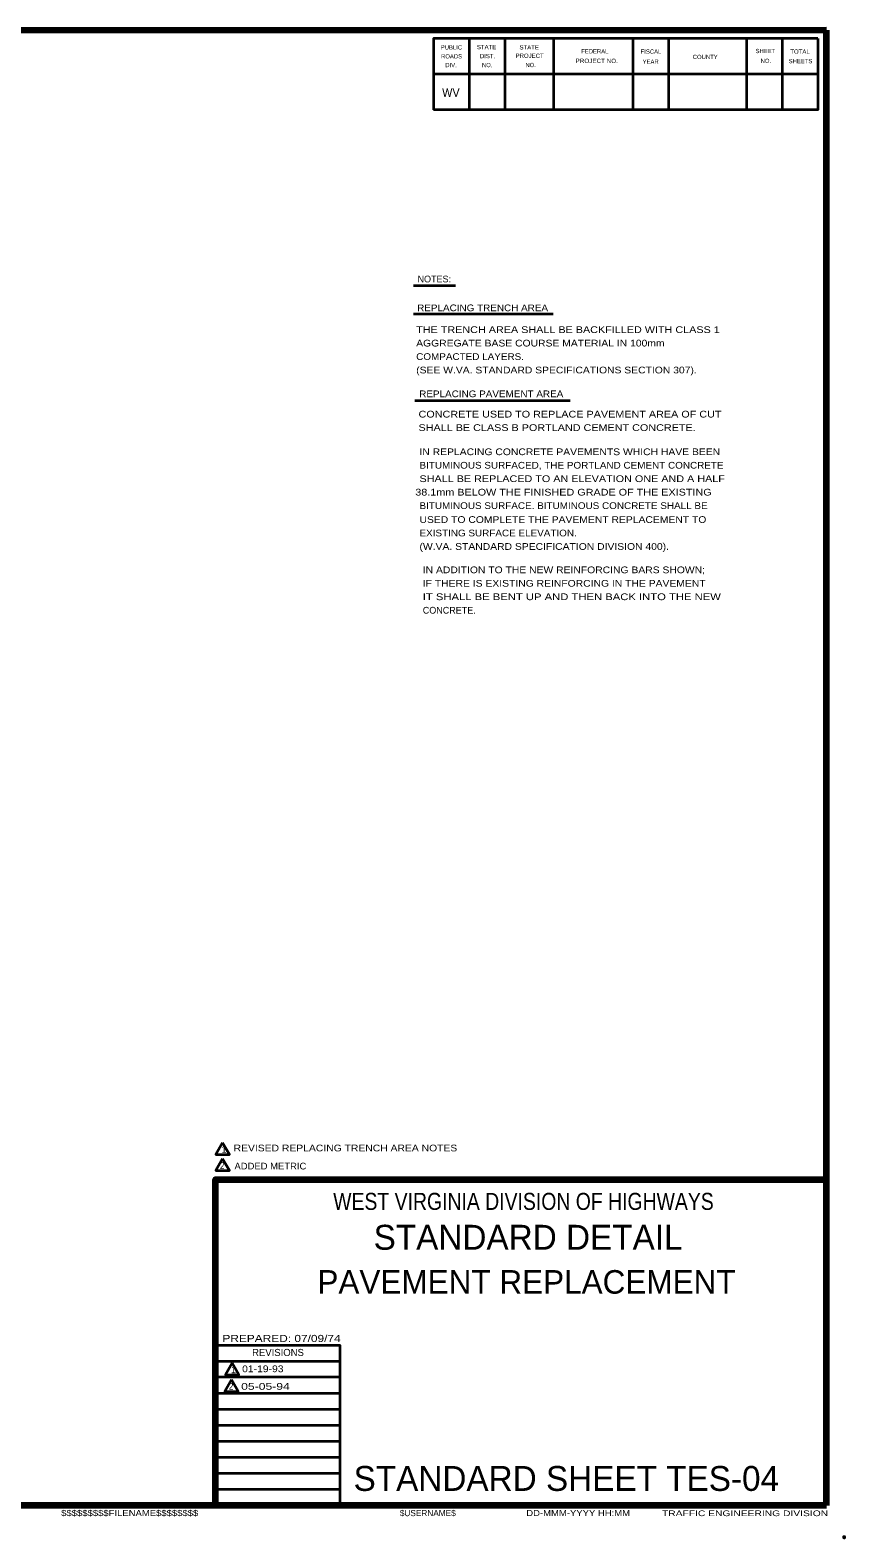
# Model space of a CAD drawing. Extents: x -617 to 238, y 23 to 567.
# Drawn here: x -52 to 238, y 23 to 560 of the extents above; entities that cross this region are included whole.
import ezdxf
from ezdxf.enums import TextEntityAlignment as Align

# ---------------------------------------------------------------- set-up
doc = ezdxf.new("R2010")
doc.units = 0
doc.header["$LTSCALE"] = 0.96
doc.header["$PDMODE"] = 32
doc.header["$PDSIZE"] = 0.48
doc.layers.add('1', color=7, linetype='Continuous', lineweight=40)
doc.layers.add('61', color=7, linetype='Continuous', lineweight=35)

msp = doc.modelspace()

# ---------------------------------------------------------------- linework, layer by layer
at = {"layer": '1', "lineweight": 158}
for q in [(231.8054, 560.3585), (231.8054, 150.5585), (-559.7946, 34.2585)]:
    msp.add_line((231.8054, 34.2585), q, dxfattribs=at)
at = {"layer": '1', "lineweight": 13}
msp.add_line((231.8054, 34.2585), (231.8054, 560.3585), dxfattribs=at)
at = {"layer": '1', "lineweight": 35}
for p, q in [((84.4359, 469.2756), (99.4217, 469.2756)), ((84.4359, 459.2218), (134.3257, 459.2218)), ((85.005, 428.3018), (140.3957, 428.3018)), ((58.3054, 85.6585), (13.8054, 85.6585)), ((58.3054, 79.9585), (13.8054, 79.9585)), ((58.3054, 74.1585), (13.8054, 74.1585)), ((58.3054, 68.4585), (13.8054, 68.4585)), ((58.3054, 62.7585), (13.8054, 62.7585)), ((58.3054, 57.0585), (13.8054, 57.0585)), ((58.3054, 51.3585), (13.8054, 51.3585)), ((58.3054, 45.6585), (13.8054, 45.6585)), ((58.3054, 39.9585), (13.8054, 39.9585))]:
    msp.add_line(p, q, dxfattribs=at)
at = {"layer": '1', "lineweight": 158}
for points in [[(231.8054, 560.3585), (-559.8946, 560.2585), (-559.7946, 34.2585)], [(13.8054, 34.2585), (13.8054, 150.5585), (231.8054, 150.5585)]]:
    msp.add_lwpolyline(points, dxfattribs=at)
at = {"layer": '1', "lineweight": 35}
for points in [[(16.3876, 163.6175), (13.9876, 159.4606), (18.7876, 159.4606)], [(16.3876, 157.8538), (13.9876, 153.6969), (18.7876, 153.6969)], [(19.7828, 85.0323), (17.3828, 80.8754), (22.1828, 80.8754)], [(19.5399, 79.0965), (17.1399, 74.9396), (21.9399, 74.9396)]]:
    msp.add_lwpolyline(points, close=True, dxfattribs=at)
msp.add_lwpolyline([(58.3054, 34.2585), (58.3054, 91.3585), (13.8054, 91.3585)], dxfattribs=at)
at = {"layer": '1'}
msp.add_point((238.1054, 22.9585), dxfattribs=at)
at = {"layer": '61'}
for p, q in [((104.3054, 557.3585), (104.3054, 531.9585)), ((117.0054, 557.3585), (117.0054, 531.9585)), ((134.4054, 557.3585), (134.4054, 531.9585)), ((162.7054, 557.3585), (162.7054, 531.9585)), ((175.4054, 557.3585), (175.4054, 531.9585)), ((203.3054, 557.3585), (203.3054, 531.9585)), ((216.0054, 557.3585), (216.0054, 531.9585)), ((228.7054, 544.6585), (91.6054, 544.6585))]:
    msp.add_line(p, q, dxfattribs=at)
at = {"layer": '61', "lineweight": 53}
for q in [(79.1054, 34.2585), (79.1054, 34.2585), (79.1054, 34.2585), (79.4054, 34.2585), (79.4054, 34.2585)]:
    msp.add_line((231.8054, 34.2585), q, dxfattribs=at)
at = {"layer": '61'}
for points in [[(228.7054, 557.3585), (91.6054, 557.3585), (91.6054, 531.9585)], [(228.7054, 557.3585), (228.7054, 531.9585), (91.6054, 531.9585)]]:
    msp.add_lwpolyline(points, dxfattribs=at)

# ---------------------------------------------------------------- texts
at = {"layer": '1'}
for s, height, width, p in [('WV', 3.048, 0.95, (94.7054, 536.5585)), ('REPLACING TRENCH AREA', 2.4, 1.1, (85.7812, 460.1271)), ('THE TRENCH AREA SHALL BE BACKFILLED WITH CLASS 1', 2.4, 1.2, (85.4396, 452.3537)), ('AGGREGATE BASE COURSE MATERIAL IN 100mm', 2.4, 1.15, (85.4396, 447.5537)), ('COMPACTED LAYERS.', 2.4, 1.1, (85.4396, 442.7537)), ('(SEE W.VA. STANDARD SPECIFICATIONS SECTION 307).', 2.4, 1.15, (85.4396, 437.9537)), ('REPLACING PAVEMENT AREA', 2.4, 1.1, (86.5172, 429.4666)), ('SHALL BE CLASS B PORTLAND CEMENT CONCRETE.', 2.4, 1.2, (86.2719, 417.4273)), ('CONCRETE USED TO REPLACE PAVEMENT AREA OF CUT', 2.4, 1.2, (86.2719, 422.2273)), ('IN REPLACING CONCRETE PAVEMENTS WHICH HAVE BEEN', 2.4, 1.15, (86.6135, 408.802)), ('BITUMINOUS SURFACED, THE PORTLAND CEMENT CONCRETE', 2.4, 1.1, (86.6135, 404.002)), ('SHALL BE REPLACED TO AN ELEVATION ONE AND A HALF', 2.4, 1.2, (86.6135, 399.202)), (' 38.1mm BELOW THE FINISHED GRADE OF THE EXISTING', 2.4, 1.2, (84.0521, 394.4021)), ('BITUMINOUS SURFACE. BITUMINOUS CONCRETE SHALL BE ', 2.4, 1.1, (86.6135, 389.602)), ('USED TO COMPLETE THE PAVEMENT REPLACEMENT TO', 2.4, 1.15, (86.6134, 384.6381)), ('EXISTING SURFACE ELEVATION. ', 2.4, 1.1, (86.6134, 379.8381)), ('(W.VA. STANDARD SPECIFICATION DIVISION 400).', 2.4, 1.15, (86.6134, 375.0381)), ('IN ADDITION TO THE NEW REINFORCING BARS SHOWN; ', 2.4, 1.15, (87.7871, 366.7007)), ('IF THERE IS EXISTING REINFORCING IN THE PAVEMENT ', 2.4, 1.15, (87.7871, 361.9007)), ('IT SHALL BE BENT UP AND THEN BACK INTO THE NEW', 2.4, 1.25, (87.7871, 357.1007)), ('PREPARED: 07/09/74', 2.537, 1.25, (16.3054, 92.5585)), ('$$$$$$$$$FILENAME$$$$$$$$', 2.2, 1.15, (-41.1946, 30.4585)), ('DD-MMM-YYYY HH:MM', 2.2, 1.15, (124.7054, 30.4585)), ('TRAFFIC ENGINEERING DIVISION', 2.031, 1.35, (173.1054, 30.4585))]:
    msp.add_text(s, height=height, dxfattribs=dict(at, width=width)).set_placement(p)
for s, height, p in [('NOTES:', 2.4, (85.9189, 470.4136)), ('CONCRETE.', 2.4, (87.7871, 352.3007)), ('REVISIONS', 2.537, (26.9054, 87.5585)), ('STANDARD SHEET TES-04', 8.881, (63.1054, 39.4585)), ('$USERNAME$', 2.2, (79.6054, 30.4585))]:
    msp.add_text(s, height=height, dxfattribs=at).set_placement(p)
for s, height, p in [('1', 2.4, (16.8784, 160.0245)), ('STANDARD DETAIL', 8.881, (125.3554, 125.4585)), ('PAVEMENT REPLACEMENT', 8.4, (124.7829, 109.7855)), ('1', 2.4, (20.2736, 81.4393))]:
    msp.add_text(s, height=height, dxfattribs=at).set_placement(p, align=Align.CENTER)
for s, height, width, p in [('REVISED REPLACING TRENCH AREA NOTES', 2.4, 1.15, (60.204, 160.5284)), ('2', 2.4, 0.9, (16.2616, 154.2608)), ('ADDED METRIC', 2.4, 1.05, (33.4359, 154.0868)), ('WEST VIRGINIA DIVISION OF HIGHWAYS', 6.089, 0.85, (123.7054, 139.6585)), ('01-19-93', 2.4, 1.15, (30.7325, 81.79)), ('2', 2.4, 0.9, (19.4139, 75.5035)), ('05-05-94', 2.4, 1.35, (31.676, 75.5151))]:
    msp.add_text(s, height=height, dxfattribs=dict(at, width=width)).set_placement(p, align=Align.CENTER)
at = {"layer": '61'}
for s, height, rotation, p in [('PUBLIC', 1.525, 0.033, (94.2054, 553.4585)), ('ROADS', 1.525, 0.124, (94.3054, 550.2585)), ('DIV.', 1.525, 359.932, (95.8054, 547.1585)), ('DIST.', 1.525, 0.056, (108.2054, 550.3585)), ('FEDERAL', 1.523, 0.007, (144.3054, 552.0585)), ('FISCAL', 1.525, 359.942, (165.5054, 551.9585)), ('YEAR', 1.523, 0.105, (166.2054, 548.3585)), ('COUNTY', 1.523, 0.069, (184.1054, 550.0585)), ('SHEET', 1.525, 0.059, (206.5054, 552.1585)), ('SHEETS', 1.523, 359.959, (218.3054, 548.5585))]:
    msp.add_text(s, height=height, rotation=rotation, dxfattribs=at).set_placement(p)
for s, rotation, width, p in [('STATE', 0.059, 1.05, (107.1054, 553.5585)), ('STATE', 0.059, 1.05, (122.3054, 553.4585)), ('NO.', 359.852, 0.9, (108.9054, 547.1585)), ('PROJECT', 359.908, 1.05, (120.9054, 550.4585)), ('NO.', 0.225, 0.9, (124.4054, 547.1585)), ('PROJECT NO.', 359.922, 1.1, (142.3054, 548.6585)), ('NO.', 359.852, 0.9, (208.3054, 548.6585)), ('TOTAL', 359.926, 1.05, (218.9054, 551.9585))]:
    msp.add_text(s, height=1.525, rotation=rotation, dxfattribs=dict(at, width=width)).set_placement(p)

doc.saveas('drawing.dxf')
